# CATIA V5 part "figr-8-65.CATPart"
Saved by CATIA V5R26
Part number: Part1
Bounding box of the stored display mesh (mm): x -53.439 to 53.439, y -63.41 to 103.633, z -17.5 to 34.5
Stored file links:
  D:\_Deepak\CATIA\CATIA V5-6R2016_Deepak\Resources\Part files\Partfiles\c08_catia_v5_6r2016_prt\figr-8-65.CATPart
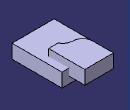
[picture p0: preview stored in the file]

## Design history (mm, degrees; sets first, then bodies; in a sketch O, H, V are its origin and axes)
Body1 (main body)
  Sketch1 on xy-plane, origin (0, 0, 0), H (1, 0, 0), V (0, 1, 0)
    line L1 (-53.4395, 63.4095) -> (53.4395, 63.4095)
    line L2 (53.4395, 63.4095) -> (53.4395, -63.4095)
    line L3 (53.4395, -63.4095) -> (-53.4395, -63.4095)
    line L4 (-53.4395, -63.4095) -> (-53.4395, 63.4095)
    axis line L5 (53.4395, -63.4095) -> (-53.4395, 63.4095)
    horizontal: L1 H, L3 H
    vertical: L2 V, L4 V
    midpoint: O L5
  Pad1: profile Sketch1, direction (0, 0, 1), length 17.5, mirrored extent
Body2
  Sketch2 on xy-plane, origin (0, 0, 0), H (1, 0, 0), V (0, 1, 0)
    line L1 (-36.9238, 103.6333) -> (-36.9238, 51.4035)
    arc A1 centre (-11.4307, 51.4035) radius 25.4931 from (-36.9238, 51.4035) to (-11.4307, 25.9104) ccw
    arc A2 centre (-11.4307, 0.4172) radius 25.4931 from (-11.4307, 25.9104) to (11.4981, 11.5602) cw
    line L2 (11.4981, 11.5602) -> (35.6176, 11.5602)
    line L3 (35.6176, 11.5602) -> (35.6176, 103.6333)
    line L4 (35.6176, 103.6333) -> (-36.9238, 103.6333)
    vertical: L1 V, L3 V
    tangency: A1 L1, A2 L1, A2 A1
    horizontal: L2 H, L4 H
  Pad2: profile Sketch2, direction (0, 0, 1), length 34.5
